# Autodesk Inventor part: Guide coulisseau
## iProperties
Author: Flavien MARTY
Shininess: 20.0
PropertySet Name: _Private Model Information
Created: 2001-10
Part Number: Guide coulisseau
Material: Par défaut
Document SubType Name: Modélisation
Designer: Flavien MARTY
Control State: 0
Master: False
Checked Out: False
PropertySet Name: Design Tracking Control
Density: 0.0
Volumn: 0.0
Area: 0.0
PropertySet Name: Model Information
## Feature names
1. Base1
